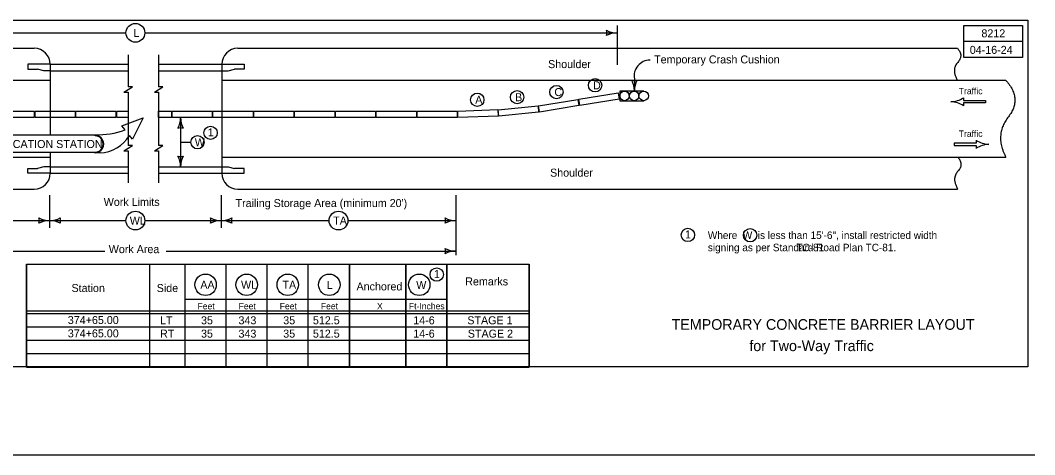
# Model space of a CAD drawing. Extents: x -2096698 to 6160, y -2144490 to 6200.
# Drawn here: x 4260 to 6160, y 5386 to 6200 of the extents above; entities that cross this region are included whole.
import ezdxf

# ---------------------------------------------------------------- set-up
doc = ezdxf.new("R2010")
doc.units = 0
for name, color, linetype in [('dsnStdNameDate', 7, 'Continuous'), ('Level 10', 7, 'Continuous'), ('Level 11', 7, 'Continuous'), ('Level 12', 7, 'Continuous'), ('Level 14', 7, 'Continuous'), ('Level 2', 7, 'Continuous'), ('Level 3', 7, 'Continuous'), ('Level 6', 7, 'Continuous'), ('Level 9', 7, 'Continuous'), ('PhoEdgeRoadPaved', 7, 'Continuous')]:
    doc.layers.add(name, color=color, linetype=linetype)

msp = doc.modelspace()

# ---------------------------------------------------------------- linework, layer by layer
at = {"layer": 'dsnStdNameDate'}
msp.add_line((6147.3, 6200.3), (6147.3, 6200.3), dxfattribs=at)
at = {"layer": 'Level 10'}
for p, q in [((3042.3, 6200.3), (6147.3, 6200.3)), ((6147.3, 6200.3), (6147.3, 5550.3)), ((4450.2, 6002.1), (4490.4, 6017.1)), ((4490.4, 6017.1), (4470.3, 5977.1)), ((4456.1, 5994.8), (4450.2, 6002.1)), ((4399.9, 5984.6), (4216.8, 5984.6)), ((4399.9, 5983.7), (4399.9, 5985.5)), ((4470.3, 5977.1), (4464.7, 5984.1)), ((4399.9, 5952.1), (4216.8, 5952.1)), ((4399.9, 5951.2), (4399.9, 5953)), ((4409.5, 5951.6), (4399.9, 5951.2))]:
    msp.add_line(p, q, dxfattribs=at)
for centre, major_axis, start_param, end_param in [((4402.8, 6141.6), (156.9, 0), 4.694293, 5.059134), ((4399.9, 5968.3), (16.3, 0), 4.712389, 7.853982), ((4399.9, 5968.3), (-15.4, 0), 1.570796, 4.712389), ((4404.9, 6021.8), (70.8, 0), 4.776871, 5.71778)]:
    msp.add_ellipse(centre, major_axis=major_axis, ratio=0.995025, start_param=start_param, end_param=end_param, dxfattribs=at)
at = {"layer": 'Level 11'}
msp.add_lwpolyline([(6137.3, 6190.3), (6137.3, 6130.3), (6027.3, 6130.3), (6027.3, 6190.3), (6137.3, 6190.3), (6137.3, 6160.3), (6027.3, 6160.3)], dxfattribs=at)
at = {"layer": 'Level 12'}
for p, q in [((4271.5, 5743.3), (4271.5, 5550.3)), ((4271.5, 5743.3), (5213.1, 5743.3)), ((4876.5, 5550.3), (4876.5, 5743.3)), ((4982.1, 5550.3), (4982.1, 5743.3)), ((5059.1, 5550.3), (5059.1, 5743.3)), ((5213.1, 5550.3), (5213.1, 5743.3))]:
    msp.add_line(p, q, dxfattribs=at)
at = {"layer": 'Level 14'}
for p, q in [((6147.3, 5550.3), (3042.3, 5550.3)), ((3025.4, 5385.8), (6160.4, 5385.8))]:
    msp.add_line(p, q, dxfattribs=at)
at = {"layer": 'Level 2'}
for p, q in [((3525.2, 6176.7), (4458, 6176.7)), ((4493, 6176.7), (5377.9, 6176.7)), ((4505.7, 6176.7), (4636.2, 6176.7)), ((5377.9, 6190.5), (5377.9, 6116.9)), ((3157.6, 6147.7), (4286.1, 6147.7)), ((4667.4, 6147.7), (6015.9, 6147.7)), ((4462.1, 6135.7), (4462.1, 6075.8)), ((4519.1, 6135.7), (4519.1, 6075.8)), ((4316.1, 6117.7), (4274.1, 6117.7)), ((4274.1, 6117.7), (4274.1, 6108.7)), ((4274.1, 6108.7), (4292.1, 6108.7)), ((4304.1, 6105.7), (4292.1, 6108.7)), ((4316.1, 6105.7), (4304.1, 6105.7)), ((4316.1, 6117.7), (4462.1, 6117.7)), ((4316.1, 6117.7), (4316.1, 5984.6)), ((4316.1, 6105.7), (4462.1, 6105.7)), ((4519.1, 6117.7), (4637.4, 6117.7)), ((4519.1, 6105.7), (4637.4, 6105.7)), ((4637.4, 6117.7), (4679.4, 6117.7)), ((4637.4, 6117.7), (4637.4, 5913.7)), ((4637.4, 6105.7), (4649.4, 6105.7)), ((4649.4, 6105.7), (4661.4, 6108.7)), ((4679.4, 6108.7), (4661.4, 6108.7)), ((4679.4, 6117.7), (4679.4, 6108.7)), ((3074, 6087.7), (4316.1, 6087.7)), ((4637.4, 6087.7), (6106.2, 6087.7)), ((5410.3, 6090.3), (5410.3, 6067.8)), ((4454.1, 6065.7), (4462.1, 6070.7)), ((4454.1, 6065.7), (4462.1, 6065.7)), ((4462.1, 6070.7), (4470.1, 6075.8)), ((4470.1, 6075.8), (4462.1, 6075.8)), ((4462.1, 6065.7), (4462.1, 6015.7)), ((4511.1, 6065.7), (4527.1, 6075.8)), ((4511.1, 6065.7), (4519.1, 6065.7)), ((4527.1, 6075.8), (4519.1, 6075.8)), ((4519.1, 6065.7), (4519.1, 6015.7)), ((5427.9, 6067.5), (5382.9, 6067.5)), ((5382.9, 6067.5), (5382.9, 6049.5)), ((5382.3, 6051.5), (5382.3, 6051.5)), ((5384.1, 6055.2), (5382.8, 6054.9)), ((5382.9, 6049.5), (5427.9, 6049.5)), ((6003, 6047.6), (6003, 6047.6)), ((6027, 6055.1), (6027, 6049.8)), ((6027, 6049.8), (6068.2, 6049.8)), ((6068.2, 6045.3), (6027, 6045.3)), ((6027, 6045.3), (6027, 6040.1)), ((6068.2, 6049.8), (6068.2, 6045.3)), ((4462.1, 6015.7), (4462.1, 5965.8)), ((4519.1, 6015.7), (4519.1, 5965.8)), ((4560.1, 6017.7), (4560.1, 5925.7)), ((4560.1, 5971.7), (4579.4, 5971.7)), ((6050.6, 5970), (6009.3, 5970)), ((6009.3, 5970), (6009.3, 5965.5)), ((6050.6, 5975.2), (6050.6, 5970)), ((6074.5, 5967.7), (6074.5, 5967.7)), ((4316.1, 5952.1), (4316.1, 5913.7)), ((4454.1, 5955.7), (4462.1, 5960.7)), ((4454.1, 5955.7), (4462.1, 5955.7)), ((4462.1, 5960.7), (4470.1, 5965.8)), ((4470.1, 5965.8), (4462.1, 5965.8)), ((4462.1, 5955.7), (4462.1, 5895.7)), ((4511.1, 5955.7), (4527.1, 5965.8)), ((4511.1, 5955.7), (4519.1, 5955.7)), ((4527.1, 5965.8), (4519.1, 5965.8)), ((4519.1, 5955.7), (4519.1, 5895.7)), ((6009.3, 5965.5), (6050.6, 5965.5)), ((6050.6, 5965.5), (6050.6, 5960.2)), ((3074, 5943.7), (4316.1, 5943.7)), ((4637.4, 5943.7), (6106.2, 5943.7)), ((4274.1, 5922.7), (4292.1, 5922.7)), ((4274.1, 5913.7), (4274.1, 5922.7)), ((4316.1, 5913.7), (4274.1, 5913.7)), ((4304.1, 5925.7), (4292.1, 5922.7)), ((4316.1, 5925.7), (4304.1, 5925.7)), ((4316.1, 5925.7), (4462.1, 5925.7)), ((4316.1, 5913.7), (4462.1, 5913.7)), ((4519.1, 5925.7), (4637.4, 5925.7)), ((4519.1, 5913.7), (4637.4, 5913.7)), ((4637.4, 5925.7), (4649.4, 5925.7)), ((4637.4, 5913.7), (4679.4, 5913.7)), ((4649.4, 5925.7), (4661.4, 5922.7)), ((4679.4, 5922.7), (4661.4, 5922.7)), ((4679.4, 5913.7), (4679.4, 5922.7)), ((3157.6, 5883.7), (4286.1, 5883.7)), ((4314.8, 5872.4), (4314.8, 5811.2)), ((4636.2, 5872.4), (4636.2, 5811.2)), ((4667.4, 5883.7), (6015.9, 5883.7)), ((5075.7, 5872.4), (5075.7, 5760.1)), ((4088.7, 5824.7), (4314.8, 5824.7)), ((4314.8, 5824.7), (4458, 5824.7)), ((4493, 5824.7), (4636.2, 5824.7)), ((4505.7, 5824.7), (4636.2, 5824.7)), ((4636.2, 5824.7), (4838.3, 5824.7)), ((4873.6, 5824.7), (5075.7, 5824.7)), ((3827.3, 5767.5), (4418.1, 5767.5)), ((4533.4, 5767.5), (5075.7, 5767.5)), ((4534.8, 5767.5), (4636.2, 5767.5)), ((4502.5, 5550.3), (4502.5, 5743.3)), ((4568.5, 5550.3), (4568.5, 5743.3)), ((4645.5, 5550.3), (4645.5, 5743.3)), ((4722.5, 5550.3), (4722.5, 5743.3)), ((4799.5, 5550.3), (4799.5, 5743.3)), ((4876.5, 5743.3), (4876.5, 5550.3)), ((4982.1, 5743.3), (4982.1, 5550.3)), ((5059.1, 5743.3), (5059.1, 5550.3)), ((4568.5, 5677.5), (5059.1, 5677.5)), ((4271.5, 5655.3), (5213.1, 5655.3)), ((4271.5, 5650.3), (5213.1, 5650.3))]:
    msp.add_line(p, q, dxfattribs=at)
for points in [[(5306.2, 6052.2), (5380.2, 6064.4), (5382.1, 6052.5), (5308.1, 6040.4)], [(5230.7, 6039.9), (5304.7, 6052), (5306.6, 6040.2), (5232.6, 6028)], [(4211.1, 6029.7), (4286.1, 6029.7), (4286.1, 6017.7), (4211.1, 6017.7)], [(4287.6, 6029.7), (4362.6, 6029.7), (4362.6, 6017.7), (4287.6, 6017.7)], [(4364.1, 6029.7), (4439.1, 6029.7), (4439.1, 6017.7), (4364.1, 6017.7)], [(4544.4, 6029.7), (4619.4, 6029.7), (4619.4, 6017.7), (4544.4, 6017.7)], [(4620.9, 6029.7), (4695.9, 6029.7), (4695.9, 6017.7), (4620.9, 6017.7)], [(4697.4, 6029.7), (4772.4, 6029.7), (4772.4, 6017.7), (4697.4, 6017.7)], [(4773.9, 6029.7), (4848.9, 6029.7), (4848.9, 6017.7), (4773.9, 6017.7)], [(4850.4, 6029.7), (4925.4, 6029.7), (4925.4, 6017.7), (4850.4, 6017.7)], [(4926.9, 6029.7), (5001.9, 6029.7), (5001.9, 6017.7), (4926.9, 6017.7)], [(5003.4, 6029.7), (5078.4, 6029.7), (5078.4, 6017.7), (5003.4, 6017.7)], [(5079.5, 6029.7), (5154.4, 6032.7), (5154.9, 6020.7), (5079.9, 6017.7)], [(5155.2, 6032.6), (5229.9, 6039.7), (5231, 6027.8), (5156.4, 6020.7)]]:
    msp.add_lwpolyline(points, close=True, dxfattribs=at)
for points in [[(4462.1, 6017.7), (4440.6, 6017.7), (4440.6, 6029.7), (4462.1, 6029.7)], [(4462.1, 6029.7), (4462.1, 6017.7)], [(4519.1, 6017.7), (4519.1, 6029.7)], [(4519.1, 6029.7), (4542.9, 6029.7), (4542.9, 6017.7), (4519.1, 6017.7)]]:
    msp.add_lwpolyline(points, dxfattribs=at)
for centre, radius in [((4475.5, 6176.7), 17.6), ((5336.8, 6078.4), 12.5), ((5116.1, 6051.2), 12.5), ((5190.7, 6056.1), 12.5), ((5264.4, 6065.7), 12.5), ((5391.9, 6058.5), 9), ((5391.9, 6058.5), 9), ((5409.9, 6058.5), 9), ((5409.9, 6058.5), 9), ((5427.9, 6058.5), 9), ((5427.9, 6058.5), 9), ((4616.3, 5989.3), 12.5), ((4591.9, 5971.7), 12.5), ((4475.5, 5824.7), 17.6), ((4856, 5824.7), 17.6), ((5510.6, 5797.8), 12.5), ((5627.2, 5797.3), 12.5), ((4607, 5704.3), 20.1), ((4684, 5704.3), 20.1), ((4761, 5704.3), 20.1), ((4838.8, 5704.3), 20.1), ((5007.3, 5704.3), 20.1), ((5040, 5723.5), 12.5)]:
    msp.add_circle(centre, radius, dxfattribs=at)
for centre, radius, start, end in [((5342.3, 6176.7), 16.4, 342.2666, 17.7333), ((5377.9, 6219.2), 42.5, 241.9275, 270), ((5377.9, 6134.2), 42.5, 90, 118.0725), ((4286.1, 6117.7), 30, 0, 90), ((4667.4, 6117.7), 30, 90, 180), ((5439.8, 6095.7), 30, 90, 190.3537), ((5410.3, 6103.5), 16.4, 252.2666, 287.7334), ((5367.8, 6067.8), 42.5, 0, 28.0725), ((5452.8, 6067.8), 42.5, 151.9275, 180), ((6001.1, 6095.9), 48.4, 272.352, 302.382), ((6001.1, 5999.3), 48.4, 57.618, 87.648), ((4517.6, 6017.7), 42.5, 331.9275, 360), ((4602.6, 6017.7), 42.5, 180, 208.0725), ((4560.1, 5982.1), 16.4, 72.2666, 107.7334), ((6076.5, 6016), 48.4, 237.618, 267.648), ((6076.5, 5919.4), 48.4, 92.352, 122.382), ((4560.1, 5961.4), 16.4, 252.2666, 287.7333), ((4517.6, 5925.7), 42.5, 360, 28.0725), ((4602.6, 5925.7), 42.5, 151.9275, 180), ((4286.1, 5913.7), 30, 270, 360), ((4667.4, 5913.7), 30, 180, 270), ((4279.2, 5824.7), 16.4, 342.2666, 17.7333), ((4314.8, 5867.2), 42.5, 241.9275, 270), ((4314.8, 5782.2), 42.5, 90, 118.0725), ((4314.8, 5867.2), 42.5, 270, 298.0725), ((4314.8, 5782.2), 42.5, 61.9275, 90), ((4350.5, 5824.7), 16.4, 162.2666, 197.7334), ((4600.6, 5824.7), 16.4, 342.2666, 17.7333), ((4636.2, 5867.2), 42.5, 241.9275, 270), ((4636.2, 5782.2), 42.5, 90, 118.0725), ((4636.2, 5867.2), 42.5, 270, 298.0725), ((4636.2, 5782.2), 42.5, 61.9275, 90), ((4671.9, 5824.7), 16.4, 162.2666, 197.7334), ((5040.1, 5824.7), 16.4, 342.2666, 17.7333), ((5075.7, 5867.2), 42.5, 241.9275, 270), ((5075.7, 5782.2), 42.5, 90, 118.0725), ((5040.1, 5767.5), 16.4, 342.2666, 17.7333), ((5075.7, 5810), 42.5, 241.9275, 270), ((5075.7, 5725), 42.5, 90, 118.0725)]:
    msp.add_arc(centre, radius, start, end, dxfattribs=at)
for points in [[(6015.9, 6147.7), (6027.7, 6133.6), (6004.1, 6108.6), (6015.4, 6087.8)], [(6106.2, 6087.7), (6137.7, 6053.3), (6084.3, 5985.2), (6106.2, 5943.7)], [(6016.3, 5943.7), (6028.1, 5929.6), (6004.5, 5904.6), (6015.9, 5883.7)]]:
    msp.add_open_spline(points, degree=2, dxfattribs=at)
at = {"layer": 'Level 3'}
for p, q in [((4271.5, 5550.3), (4271.5, 5743.3)), ((4271.5, 5743.3), (5213.1, 5743.3)), ((5213.1, 5743.3), (5213.1, 5550.3))]:
    msp.add_line(p, q, dxfattribs=at)
at = {"layer": 'Level 9'}
for p, q in [((4271.5, 5625.3), (5213.1, 5625.3)), ((4271.5, 5600.3), (5213.1, 5600.3)), ((4271.5, 5575.3), (5213.1, 5575.3)), ((4271.5, 5550), (5213.1, 5550))]:
    msp.add_line(p, q, dxfattribs=at)

# ---------------------------------------------------------------- texts
at = {"layer": 'dsnStdNameDate'}
for s, p in [('8212', (6060.5, 6168.3)), ('04-16-24', (6038.7, 6137.3))]:
    msp.add_text(s, height=15, dxfattribs=at).set_placement(p)
at = {"layer": 'Level 10'}
msp.add_text('LOCATION STATION', height=15, dxfattribs=at).set_placement((4219, 5960.8))
at = {"layer": 'Level 3'}
for s, height, p in [('L', 15, (4471.6, 6169.2)), ('Shoulder', 15, (5248.7, 6110.6)), ('Temporary Crash Cushion', 15, (5447.3, 6119.4)), ('D', 15, (5332.9, 6070.9)), ('B', 15, (5186.8, 6048.6)), ('C', 15, (5260.5, 6058.2)), ('Traffic', 12, (6018, 6061.6)), ('A', 15, (5112.2, 6043.7)), ('1', 15, (4611.1, 5982.7)), ('Traffic', 12, (6018, 5981.7)), ('W', 15, (4586.8, 5964.2)), ('Shoulder', 15, (5252.4, 5907.1)), ('Work Limits', 15, (4416.2, 5852.2)), ("Trailing Storage Area (minimum 20')", 15, (4663.2, 5850.1)), ('WL', 15, (4465, 5817.2)), ('TA', 15, (4846.1, 5817.2)), ('1', 15, (5505.3, 5791.2)), ('Where  W  is less than 15\'-6", install restricted width', 14, (5548, 5790.3)), ('Work Area', 15, (4425.6, 5763.7)), ('signing as per Standard Road Plan TC-81.', 14, (5548, 5767.3)), ('                                TC-81', 14, (5547.3, 5767.3)), ('1', 15, (5034.7, 5716.9)), ('Station', 15, (4355.9, 5690.8)), ('Side', 15, (4515.5, 5690.8)), ('AA', 15, (4597.2, 5696.8)), ('WL', 15, (4673.5, 5696.8)), ('TA', 15, (4751.1, 5696.8)), ('L', 15, (4833.9, 5696.4)), ('Anchored', 15, (4889.8, 5693.8)), ('W', 15, (5001.7, 5696.4)), ('Remarks', 15, (5093.5, 5703.2)), ('Feet', 12, (4592, 5658.3)), ('Feet', 12, (4669, 5658.3)), ('Feet', 12, (4746, 5658.3)), ('Feet', 12, (4823, 5658.3)), ('X', 12, (4928.1, 5658.3)), ('Ft-Inches', 12, (4988, 5658.3))]:
    msp.add_text(s, height=height, dxfattribs=at).set_placement(p)
at = {"layer": 'Level 6'}
for s, p in [('TEMPORARY CONCRETE BARRIER LAYOUT', (5480, 5620)), ('for Two-Way Traffic', (5625.7, 5580))]:
    msp.add_text(s, height=20, dxfattribs=at).set_placement(p)
at = {"layer": 'PhoEdgeRoadPaved'}
for s, p in [('374+65.00', (4348.9, 5630.8)), ('LT', (4521.7, 5630.3)), ('35', (4598.5, 5630.3)), ('343', (4668.7, 5630.3)), ('35', (4752.5, 5630.3)), ('512.5', (4808.1, 5630.3)), ('14-6', (4996.1, 5630.3)), ('STAGE 1', (5097.4, 5630.3)), ('374+65.00', (4348.9, 5605.8)), ('RT', (4521.7, 5605.3)), ('35', (4598.5, 5605.3)), ('343', (4668.7, 5605.3)), ('35', (4752.5, 5605.3)), ('512.5', (4808.1, 5605.3)), ('14-6', (4996.1, 5605.3)), ('STAGE 2', (5098.3, 5605.3))]:
    msp.add_text(s, height=15, dxfattribs=at).set_placement(p)

doc.saveas('drawing.dxf')
